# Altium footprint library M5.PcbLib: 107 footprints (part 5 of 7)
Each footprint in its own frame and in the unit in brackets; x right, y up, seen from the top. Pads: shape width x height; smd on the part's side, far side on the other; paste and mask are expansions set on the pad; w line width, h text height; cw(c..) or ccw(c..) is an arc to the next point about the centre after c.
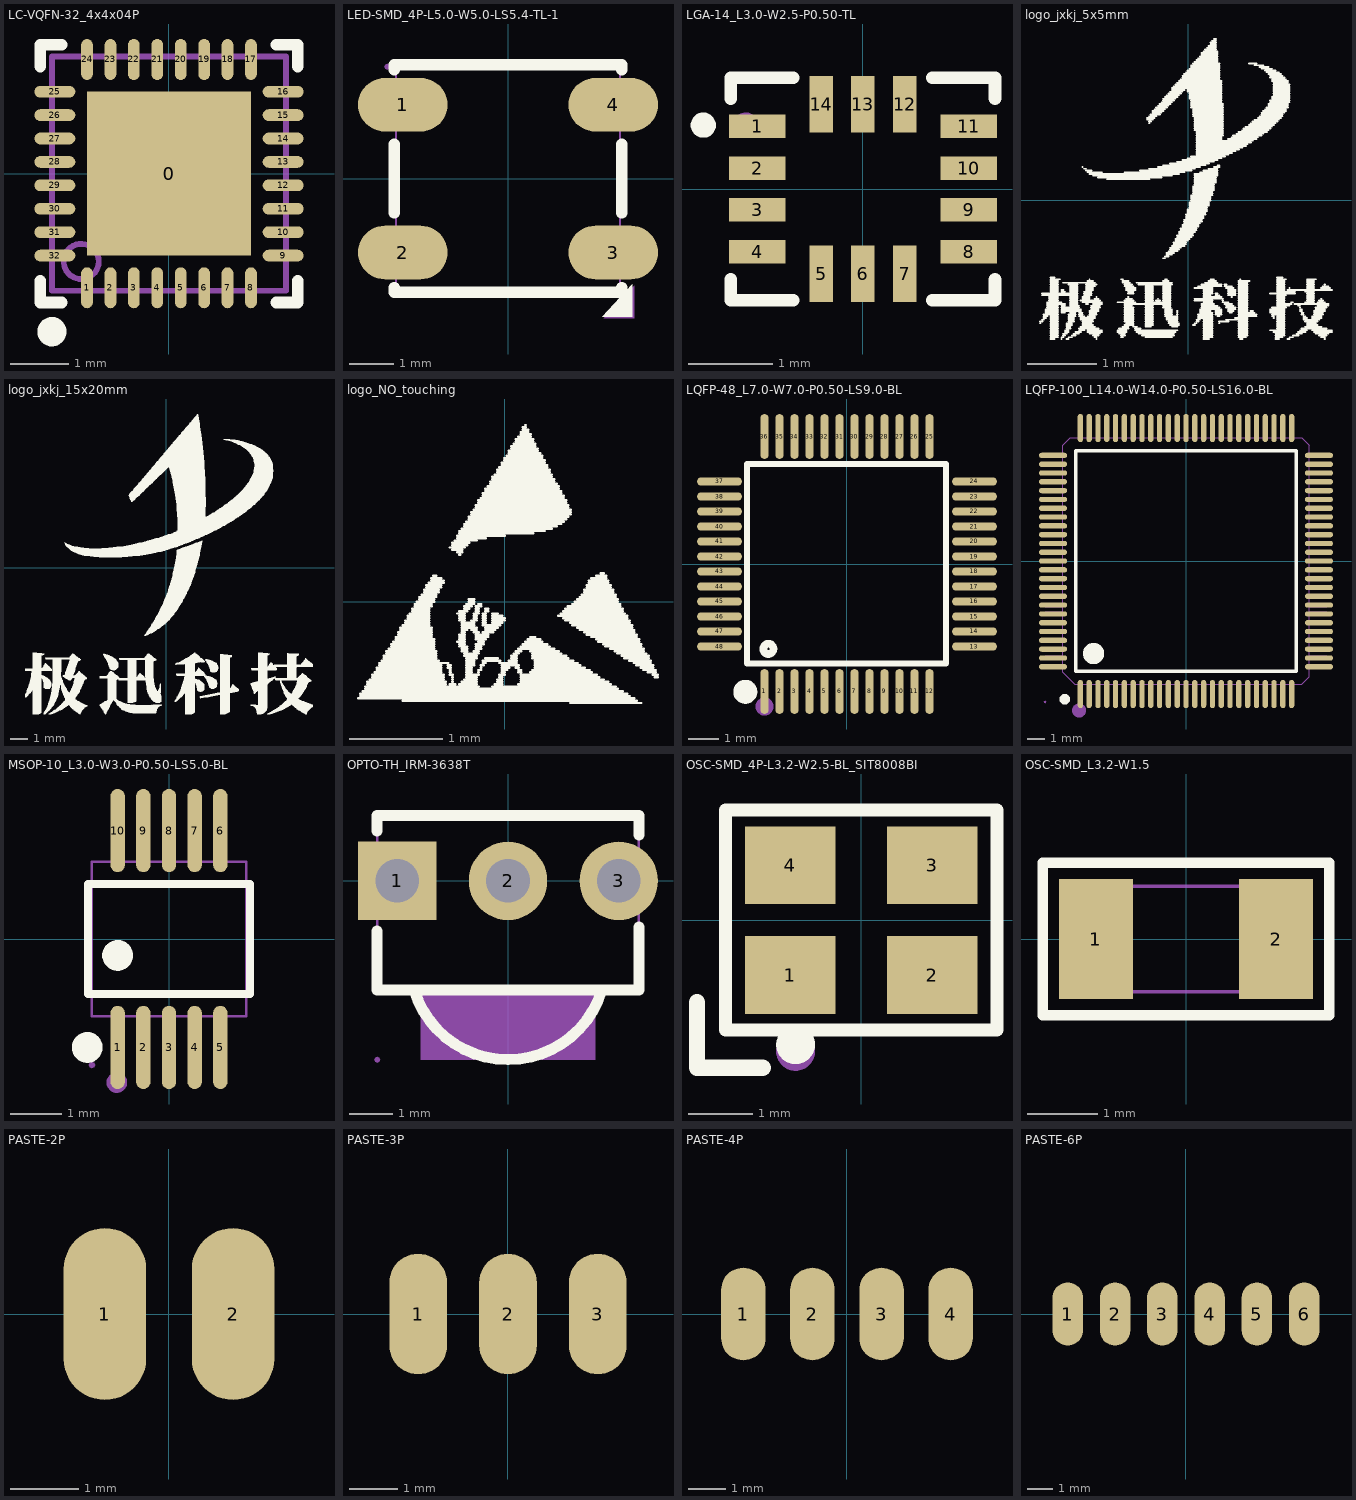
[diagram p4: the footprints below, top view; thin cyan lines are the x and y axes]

## LC-VQFN-32_4x4x04P [mm]
pads (33):
  rect 2.8x2.8 smd paste-0.025 mask+0.051: 0(0,0)
  oval 0.2x0.7 smd paste-0.025 mask+0.051: 1(-1.4,-1.95) 2(-1,-1.95) 3(-0.6,-1.95) 4(-0.2,-1.95) 5(0.2,-1.95) 6(0.6,-1.95) 7(1,-1.95) 8(1.4,-1.95) 17(1.4,1.95) 18(1,1.95) 19(0.6,1.95) 20(0.2,1.95) 21(-0.2,1.95) 22(-0.6,1.95) 23(-1,1.95) 24(-1.4,1.95)
  oval 0.7x0.2 smd paste-0.025 mask+0.051: 9(1.95,-1.4) 10(1.95,-1) 11(1.95,-0.6) 12(1.95,-0.2) 13(1.95,0.2) 14(1.95,0.6) 15(1.95,1) 16(1.95,1.4) 25(-1.95,1.4) 26(-1.95,1) 27(-1.95,0.6) 28(-1.95,0.2) 29(-1.95,-0.2) 30(-1.95,-0.6) 31(-1.95,-1) 32(-1.95,-1.4)
Top Overlay:
  circle w0.25: c-2,-2.7 r0.125
  lines w0.2: -2.2,-1.83 -2.2,-2.2 -1.83,-2.2 ; -2.2,1.83 -2.2,2.2 -1.83,2.2 ; 1.83,-2.2 2.2,-2.2 2.2,-1.83 ; 1.83,2.2 2.2,2.2 2.2,1.83
Mechanical 13:
  circle w0.1: c-1.5,-1.5 r0.3
  lines w0.1: -2,-2 2,-2 2,2 -2,2 -2,-2

## LED-SMD_4P-L5.0-W5.0-LS5.4-TL-1 [mm]
pads (4):
  oval 2x1.2 smd paste+0 mask+0.05: 1(-2.35,1.65) 2(-2.35,-1.65) 3(2.35,-1.65) 4(2.35,1.65)
Top Overlay:
  region: 2.101,-3.085 2.775,-3.085 2.775,-2.361
  lines w0.254: -2.54,-2.431 -2.54,-2.54 2.54,-2.54 2.54,-2.431 ; -2.54,-0.769 -2.54,0.769 ; -2.54,2.431 -2.54,2.54 2.54,2.54 2.54,2.431 ; 2.54,-0.769 2.54,0.769
Mechanical 6:
  region: 2.143,-3.113 2.816,-3.113 2.816,-2.39
  region: -2.028,1.912 -2.062,1.882 -2.065,1.355 -1.957,1.354 -1.963,1.808
  region: -2.029,1.912 -1.804,1.909 -1.698,1.859 -1.634,1.8 -1.602,1.724 -1.575,1.639 -1.577,1.488 -1.609,1.387 -1.645,1.33 -1.709,1.273 -1.828,1.237 -2.035,1.241 -2.062,1.264 -2.064,1.293 -2.064,1.359 -1.961,1.356 -1.964,1.341 -1.84,1.338 -1.765,1.362 -1.722,1.398 -1.703,1.445 -1.68,1.514 -1.683,1.627 -1.728,1.746 -1.766,1.788 -1.83,1.806 -1.962,1.808
  region: -2.581,1.915 -2.615,1.885 -2.618,1.358 -2.51,1.357 -2.516,1.81
  region: -2.582,1.915 -2.357,1.912 -2.251,1.862 -2.187,1.803 -2.155,1.727 -2.128,1.642 -2.13,1.491 -2.162,1.39 -2.198,1.333 -2.262,1.276 -2.381,1.239 -2.588,1.244 -2.615,1.267 -2.617,1.296 -2.617,1.362 -2.514,1.359 -2.517,1.344 -2.393,1.341 -2.318,1.365 -2.275,1.401 -2.256,1.448 -2.233,1.517 -2.236,1.63 -2.281,1.749 -2.319,1.791 -2.383,1.809 -2.515,1.81
  region: -2.723,1.909 -2.759,1.912 -2.782,1.894 -2.964,1.433 -3.144,1.89 -3.175,1.911 -3.199,1.911 -3.219,1.899 -3.231,1.875 -3.229,1.843 -3.01,1.26 -2.993,1.249 -2.972,1.241 -2.949,1.241 -2.926,1.249 -2.914,1.277 -2.695,1.856 -2.693,1.873 -2.707,1.896
Mechanical 15:
  region: -2.635,2.5 -2.654,2.454 -2.7,2.435 -2.746,2.454 -2.765,2.5 -2.746,2.546 -2.7,2.565 -2.654,2.546
  region: 1.8,2.1 2.7,2.1 2.7,1.2 1.8,1.2
  region: 1.8,-1.2 2.7,-1.2 2.7,-2.1 1.8,-2.1
  region: -2.7,-1.2 -1.8,-1.2 -1.8,-2.1 -2.7,-2.1
  region: -2.7,2.1 -1.8,2.1 -1.8,1.2 -2.7,1.2
  lines w0.051: -2.5,-2.5 -2.5,2.5 2.5,2.5 2.5,-2.5 -2.5,-2.5
3D body: height 1.6, standoff 0, extent -2.667,-2.5 2.733,2.5

## LGA-14_L3.0-W2.5-P0.50-TL [mm]
pads (14):
  rect 0.675x0.28 smd: 1(-1.262,0.75) 2(-1.262,0.25) 3(-1.262,-0.25) 4(-1.262,-0.75) 8(1.262,-0.75) 9(1.262,-0.25) 10(1.262,0.25) 11(1.262,0.75)
  rect 0.28x0.675 smd: 5(-0.5,-1.012) 6(0,-1.012) 7(0.5,-1.012) 12(0.5,1.012) 13(0,1.012) 14(-0.5,1.012)
Top Overlay:
  circle w0.15: c-1.905,0.762 r0.075
  lines w0.152: -1.576,-1.08 -1.576,-1.326 -0.831,-1.326 ; -1.576,1.08 -1.576,1.326 -0.831,1.326 ; 0.83,-1.326 1.576,-1.326 1.576,-1.08 ; 0.83,1.326 1.576,1.326 1.576,1.08
Mechanical 6:
  circle w0.15: c-1.397,0.762 r0.075
3D body: height 0.86, standoff -0.02, extent -1.5,-1.23 1.5,1.27

## logo_jxkj_5x5mm [mm]
Top Overlay:
  drawing of 613 lines, arcs and shapes, not listed

## logo_jxkj_15x20mm [mm]
Top Overlay:
  drawing of 2469 lines, arcs and shapes, not listed

## logo_NO_touching [mm]
Top Overlay:
  drawing of 283 lines, arcs and shapes, not listed

## LQFP-48_L7.0-W7.0-P0.50-LS9.0-BL [mm]
pads (48):
  oval 0.27x1.5 smd paste+0 mask+0.05: 1(-2.75,-4.25) 2(-2.25,-4.25) 3(-1.75,-4.25) 4(-1.25,-4.25) 5(-0.75,-4.25) 6(-0.25,-4.25) 7(0.25,-4.25) 8(0.75,-4.25) 9(1.25,-4.25) 10(1.75,-4.25) 11(2.25,-4.25) 12(2.75,-4.25) 25(2.75,4.25) 26(2.25,4.25) 27(1.75,4.25) 28(1.25,4.25) 29(0.75,4.25) 30(0.25,4.25) 31(-0.25,4.25) 32(-0.75,4.25) 33(-1.25,4.25) 34(-1.75,4.25) 35(-2.25,4.25) 36(-2.75,4.25)
  oval 1.5x0.27 smd paste+0 mask+0.05: 13(4.25,-2.75) 14(4.25,-2.25) 15(4.25,-1.75) 16(4.25,-1.25) 17(4.25,-0.75) 18(4.25,-0.25) 19(4.25,0.25) 20(4.25,0.75) 21(4.25,1.25) 22(4.25,1.75) 23(4.25,2.25) 24(4.25,2.75) 37(-4.25,2.75) 38(-4.25,2.25) 39(-4.25,1.75) 40(-4.25,1.25) 41(-4.25,0.75) 42(-4.25,0.25) 43(-4.25,-0.25) 44(-4.25,-0.75) 45(-4.25,-1.25) 46(-4.25,-1.75) 47(-4.25,-2.25) 48(-4.25,-2.75)
Top Overlay:
  circle w0.254: c-2.62,-2.83 r0.17
  lines w0.2: -2.896,3.34 3.302,3.34 3.302,-3.315 -3.327,-3.315 -3.327,3.34 -2.565,3.34
  lines w0.4: -3.39,-4.06 ccw(c-3.389,-4.26) -3.389,-4.46 ccw(c-3.389,-4.26) -3.387,-4.06
Mechanical 6:
  circle w0.3: c-2.75,-4.75 r0.15
3D body: height 1.45, standoff 0, extent -4.503,-4.503 4.503,4.503

## LQFP-100_L14.0-W14.0-P0.50-LS16.0-BL [mm]
pads (100):
  oval 0.3x1.6 smd: 1(-6,-7.55) 2(-5.5,-7.55) 3(-5,-7.55) 4(-4.5,-7.55) 5(-4,-7.55) 6(-3.5,-7.55) 7(-3,-7.55) 8(-2.5,-7.55) 9(-2,-7.55) 10(-1.5,-7.55) 11(-1,-7.55) 12(-0.5,-7.55) 13(0,-7.55) 14(0.5,-7.55) 15(1,-7.55) 16(1.5,-7.55) 17(2,-7.55) 18(2.5,-7.55) 19(3,-7.55) 20(3.5,-7.55) 21(4,-7.55) 22(4.5,-7.55) 23(5,-7.55) 24(5.5,-7.55) 25(6,-7.55) 51(6,7.55) 52(5.5,7.55) 53(5,7.55) 54(4.5,7.55) 55(4,7.55) 56(3.5,7.55) 57(3,7.55) 58(2.5,7.55) 59(2,7.55) 60(1.5,7.55) 61(1,7.55) 62(0.5,7.55) 63(0,7.55) 64(-0.5,7.55) 65(-1,7.55) 66(-1.5,7.55) 67(-2,7.55) 68(-2.5,7.55) 69(-3,7.55) 70(-3.5,7.55) 71(-4,7.55) 72(-4.5,7.55) 73(-5,7.55) 74(-5.5,7.55) 75(-6,7.55)
  oval 1.6x0.3 smd: 26(7.55,-6) 27(7.55,-5.5) 28(7.55,-5) 29(7.55,-4.5) 30(7.55,-4) 31(7.55,-3.5) 32(7.55,-3) 33(7.55,-2.5) 34(7.55,-2) 35(7.55,-1.5) 36(7.55,-1) 37(7.55,-0.5) 38(7.55,0) 39(7.55,0.5) 40(7.55,1) 41(7.55,1.5) 42(7.55,2) 43(7.55,2.5) 44(7.55,3) 45(7.55,3.5) 46(7.55,4) 47(7.55,4.5) 48(7.55,5) 49(7.55,5.5) 50(7.55,6) 76(-7.55,6) 77(-7.55,5.5) 78(-7.55,5) 79(-7.55,4.5) 80(-7.55,4) 81(-7.55,3.5) 82(-7.55,3) 83(-7.55,2.5) 84(-7.55,2) 85(-7.55,1.5) 86(-7.55,1) 87(-7.55,0.5) 88(-7.55,0) 89(-7.55,-0.5) 90(-7.55,-1) 91(-7.55,-1.5) 92(-7.55,-2) 93(-7.55,-2.5) 94(-7.55,-3) 95(-7.55,-3.5) 96(-7.55,-4) 97(-7.55,-4.5) 98(-7.55,-5) 99(-7.55,-5.5) 100(-7.55,-6)
Top Overlay:
  lines w0.2: -6.25,-6.25 6.25,-6.25 6.25,6.25 -6.25,6.25 -6.25,-6.25
  lines w0.3: -6.883,-7.696 ccw(c-6.882,-7.846) -6.882,-7.996 ccw(c-6.882,-7.846) -6.881,-7.696
  lines w0.6: -5.25,-4.95 ccw(c-5.248,-5.25) -5.248,-5.55 ccw(c-5.248,-5.25) -5.245,-4.95
Mechanical 6:
  circle w0.4: c-6.071,-8.484 r0.2
Mechanical 15:
  drawing of 209 lines, arcs and shapes, not listed
3D body: height 1.6, standoff 0, extent -8.001,-8.001 7.999,7.999

## MSOP-10_L3.0-W3.0-P0.50-LS5.0-BL [mm]
pads (10):
  oval 0.28x1.62 smd: 1(-1,-2.11) 2(-0.5,-2.11) 3(0,-2.11) 4(0.5,-2.11) 5(1,-2.11) 6(1,2.11) 7(0.5,2.11) 8(0,2.11) 9(-0.5,2.11) 10(-1,2.11)
Top Overlay:
  circle w0.3: c-1.592,-2.11 r0.15
  circle w0.3: c-1,-0.319 r0.15
  lines w0.152: -1.576,-1.071 1.576,-1.071 1.576,1.071 -1.576,1.071 -1.576,-1.071
Mechanical 6:
  circle w0.2: c-1.016,-2.794 r0.1
Mechanical 15:
  region: 0.888,1.91 0.888,1.49 1.112,1.49 1.112,1.91
  region: 0.888,2.45 0.888,1.9 1.112,1.9 1.112,2.45
  region: 0.388,1.91 0.388,1.49 0.612,1.49 0.612,1.91
  region: 0.388,2.45 0.388,1.9 0.612,1.9 0.612,2.45
  region: -0.112,1.91 -0.112,1.49 0.112,1.49 0.112,1.91
  region: -0.112,2.45 -0.112,1.9 0.112,1.9 0.112,2.45
  region: -0.612,1.91 -0.612,1.49 -0.388,1.49 -0.388,1.91
  region: -0.612,2.45 -0.612,1.9 -0.388,1.9 -0.388,2.45
  region: -1.112,1.91 -1.112,1.49 -0.888,1.49 -0.888,1.91
  region: -1.112,2.45 -1.112,1.9 -0.888,1.9 -0.888,2.45
  region: 0.888,-1.91 0.888,-1.49 1.112,-1.49 1.112,-1.91
  region: 0.888,-2.45 0.888,-1.9 1.112,-1.9 1.112,-2.45
  region: 0.388,-1.91 0.388,-1.49 0.612,-1.49 0.612,-1.91
  region: 0.388,-2.45 0.388,-1.9 0.612,-1.9 0.612,-2.45
  region: -0.112,-1.91 -0.112,-1.49 0.112,-1.49 0.112,-1.91
  region: -0.112,-2.45 -0.112,-1.9 0.112,-1.9 0.112,-2.45
  region: -0.612,-1.91 -0.612,-1.49 -0.388,-1.49 -0.388,-1.91
  region: -0.612,-2.45 -0.612,-1.9 -0.388,-1.9 -0.388,-2.45
  region: -1.112,-1.91 -1.112,-1.49 -0.888,-1.49 -0.888,-1.91
  region: -1.112,-2.45 -1.112,-1.9 -0.888,-1.9 -0.888,-2.45
  region: -1.435,-2.45 -1.454,-2.496 -1.5,-2.515 -1.546,-2.496 -1.565,-2.45 -1.546,-2.404 -1.5,-2.385 -1.454,-2.404
  lines w0.051: -1.5,-1.5 1.5,-1.5 1.5,1.5 -1.5,1.5 -1.5,-1.5
3D body: height 0.93, standoff 0, extent -1.5,-2.45 1.5,2.45

## OPTO-TH_IRM-3638T [mm]
pads (3):
  rect 1.8x1.8 hole 1: 1(-2.54,0)
  round 1.8 hole 1: 2(0,0) 3(2.54,0)
Top Overlay:
  lines w0.254: -3,-1.15 -3,-2.5 3,-2.5 3,-1.054 ; -3,1.15 -3,1.5 3,1.5 3,1.054 ; -2.153,-2.504 ccw(c0,-1.85) 2.154,-2.5
Mechanical 6:
  region: -2,-2.5 2,-2.5 2,-4.1 -2,-4.1
Mechanical 15:
  region: -2.935,-4.1 -2.954,-4.146 -3,-4.165 -3.046,-4.146 -3.065,-4.1 -3.046,-4.054 -3,-4.035 -2.954,-4.054
  region: -2.79,0.2 -2.29,0.2 -2.29,-0.2 -2.79,-0.2
  region: -0.25,0.2 0.25,0.2 0.25,-0.2 -0.25,-0.2
  region: 2.29,0.2 2.79,0.2 2.79,-0.2 2.29,-0.2
  lines w0.051: 1.6,-2.5 cw(c0,-2.5) -1.6,-2.5 -3,-2.5 -3,1.5 3,1.5 3,-2.5 1.6,-2.5
3D body: height 8.25, standoff -22.67, extent -3,-3.949 3,1.651

## OSC-SMD_4P-L3.2-W2.5-BL_SIT8008BI [mm]
pads (4):
  rect 1.4x1.2 smd: 1(-1.1,-0.85) 2(1.1,-0.85) 3(1.1,0.85) 4(-1.1,0.85)
Top Overlay:
  lines w0.203: -2.1,-1.7 2.101,-1.7 2.101,1.7 -2.1,1.7 -2.1,-1.7
  lines w0.254: -2.54,-1.27 -2.54,-2.286 -1.524,-2.286
  lines w0.3: -1.016,-1.778 ccw(c-1.015,-1.928) -1.015,-2.078 ccw(c-1.015,-1.928) -1.013,-1.778
Mechanical 6:
  circle w0.3: c-1.016,-2.032 r0.15

## OSC-SMD_L3.2-W1.5 [mm]
pads (2):
  rect 1.05x1.7 smd: 1(-1.275,0) 2(1.275,0)
Top Overlay:
  lines w0.152: -2.029,-1.079 -2.029,1.079 2.029,1.079 2.029,-1.079 -2.029,-1.079
Mechanical 15:
  region: -1.535,-0.75 -1.554,-0.796 -1.6,-0.815 -1.646,-0.796 -1.665,-0.75 -1.646,-0.704 -1.6,-0.685 -1.554,-0.704
  region: -0.85,-0.75 -0.85,0.75 -1.5,0.75 -1.5,-0.75
  region: 0.85,-0.75 0.85,0.75 1.5,0.75 1.5,-0.75
  lines w0.051: -1.6,-0.75 -1.6,0.75 1.6,0.75 1.6,-0.75 -1.6,-0.75

## PASTE-2P [mm]
pads (2):
  oval 1.2x2.5 smd: 1(-0.931,0) 2(0.931,0)

## PASTE-3P [mm]
pads (3):
  oval 1.2x2.5 smd: 1(-1.863,0) 2(0,0) 3(1.863,0)

## PASTE-4P [mm]
pads (4):
  oval 1.2x2.5 smd: 1(-2.794,0) 2(-0.931,0) 3(0.931,0) 4(2.794,0)

## PASTE-6P [mm]
pads (6):
  oval 1.2x2.5 smd: 1(-4.657,0) 2(-2.795,0) 3(-0.932,0) 4(0.93,0) 5(2.795,0) 6(4.658,0)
